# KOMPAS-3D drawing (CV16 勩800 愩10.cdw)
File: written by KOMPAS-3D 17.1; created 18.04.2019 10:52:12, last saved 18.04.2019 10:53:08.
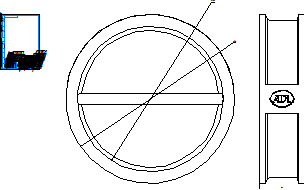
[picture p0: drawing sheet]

Sheet 1: A4, portrait

Title block, sheet 1: name: CV16 Ду800 Ру10; material: Внимание! Данный продукт является объектом авторского права ООО «Торговый Дом АДЛ». / Запрещается изменение, копирование, распространение / (в том числе путем копирования на другие сайты и ресурсы в Интернете) / или любое иное использование информации и объектов без предварительного / согласия правообладателя (ООО «Торговый Дом АДЛ»).; mass: 818,45; sheets: 1; organisation: ООО "Торговый дом АДЛ"; sheet format: A4

Views: Вид 1, Проекционный вид 2
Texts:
  user
Dimensions and other numbers on the sheet: 786,8; 911; 241; 1:1; 1; 818,45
